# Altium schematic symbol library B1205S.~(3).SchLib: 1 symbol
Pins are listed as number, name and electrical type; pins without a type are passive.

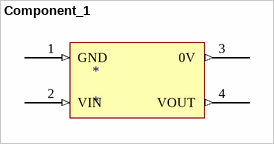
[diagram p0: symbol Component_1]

## Component_1
designator *
footprint Model Name (Footprint not found)
pins: 1 GND (in), 2 VIN (in), 3 0V (out), 4 VOUT (out)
